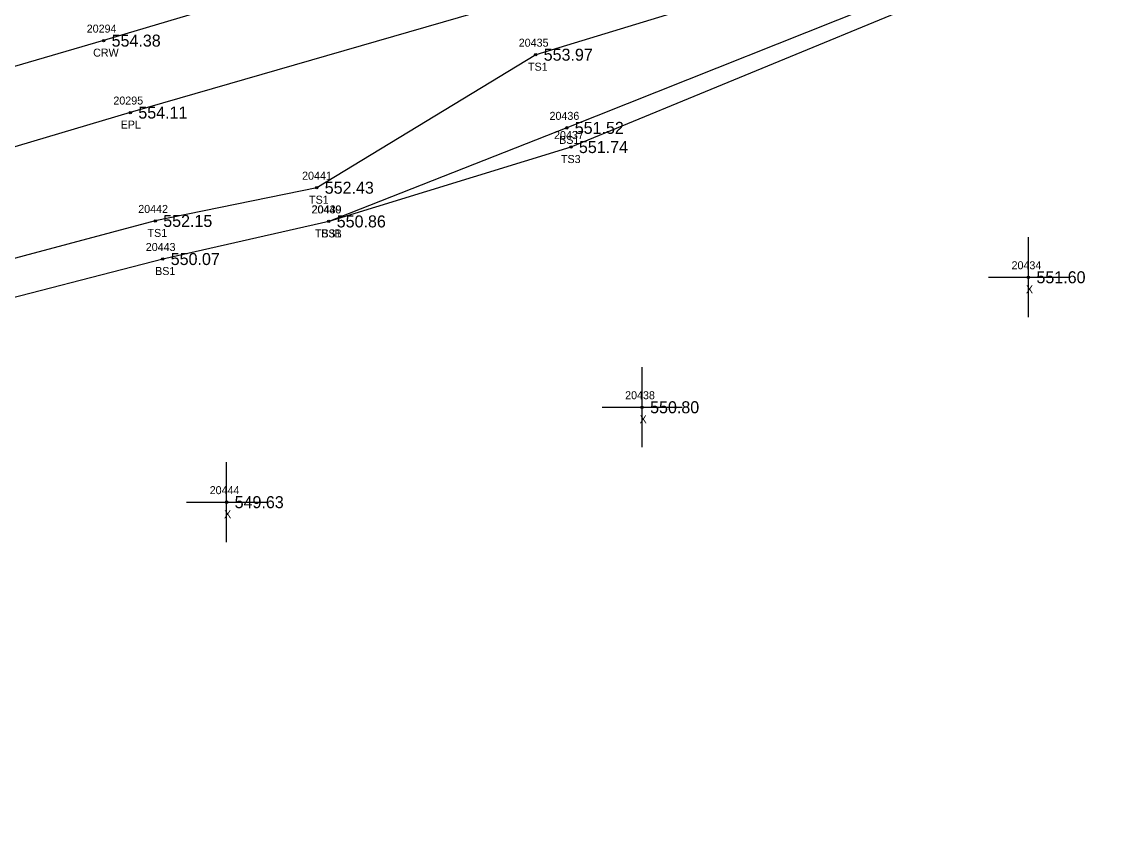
# Model space of a CAD drawing. Extents: x 1540443 to 1541844, y 887157 to 888162.
# Drawn here: x 1541377.9 to 1541515.8, y 887652.8 to 887753.4 of the extents above; entities that cross this region are included whole.
import ezdxf

# ---------------------------------------------------------------- set-up
doc = ezdxf.new("R2010")
doc.units = 0
for name, color, linetype in [('RD_DTM_BkLn1', 7, 'Continuous'), ('RD_DTM_BkLn2', 7, 'Continuous'), ('RD_DTM_BkLn_txCode', 7, 'Continuous'), ('RD_EX_Misc', 7, 'Continuous'), ('RD_EX_Misc_txCode', 7, 'Continuous'), ('RD_EX_Road', 7, 'Continuous'), ('RD_EX_Road_txCode', 7, 'Continuous'), ('RD_EX_TX_Misc_ELEV', 7, 'Continuous'), ('RD_EX_TX_Road_ELEV', 7, 'Continuous'), ('RD_HC_Survey_ELEV', 7, 'Continuous'), ('RD_HC_Survey_txCode', 7, 'Continuous'), ('RD_SMD_Locator', 7, 'Continuous')]:
    doc.layers.add(name, color=color, linetype=linetype)

msp = doc.modelspace()

# ---------------------------------------------------------------- linework, layer by layer
at = {"layer": 'RD_DTM_BkLn1'}
msp.add_lwpolyline([(1541819.64, 887879.04), (1541771.84, 887865.01), (1541723.55, 887850.95), (1541675.82, 887836.26), (1541627.89, 887822.08), (1541580.01, 887807.87), (1541531.93, 887793.38), (1541484.13, 887778.91), (1541435.66, 887765.21), (1541388.1, 887751.04), (1541339.55, 887736.89), (1541291.46, 887723.08), (1541243.5, 887708.82), (1541195.27, 887694.78), (1541169.43, 887686.85)], dxfattribs=at)
at = {"layer": 'RD_DTM_BkLn2'}
for points in [[(1541824.97, 887864.95), (1541773.24, 887848.9), (1541728.33, 887834.59), (1541680.22, 887820.65), (1541632.2, 887806.6), (1541586.15, 887794.2), (1541535.56, 887777.78), (1541490.03, 887763.87), (1541442.11, 887749.28), (1541414.74, 887732.66), (1541394.55, 887728.51), (1541346.01, 887715.56), (1541298.68, 887704.05), (1541256.52, 887687.99), (1541253.67, 887682.12), (1541204.18, 887671.81), (1541185.24, 887668.7), (1541173.43, 887674.53)], [(1541826.01, 887862.16), (1541773.99, 887846.34), (1541729.05, 887832.97), (1541681.03, 887818.46), (1541632.94, 887804.51), (1541587.44, 887789.41), (1541536.78, 887773.27), (1541491.06, 887758.08), (1541445.99, 887740.14), (1541416.24, 887728.45), (1541395.49, 887723.75), (1541347.04, 887711.22), (1541300.85, 887696.02), (1541261.64, 887680.26), (1541255.59, 887675.42), (1541206.42, 887663.07), (1541174, 887652.79)], [(1541826.81, 887859.86), (1541774.16, 887844.66), (1541729.81, 887830.83), (1541681.55, 887816.28), (1541633.12, 887801.68), (1541588.74, 887788.35), (1541537.56, 887771.08), (1541491.43, 887756.24), (1541446.51, 887737.74), (1541416.24, 887728.45)]]:
    msp.add_lwpolyline(points, dxfattribs=at)
at = {"layer": 'RD_EX_Misc'}
for p, q in [((1541503.7, 887716.47), (1541503.7, 887726.47)), ((1541498.7, 887721.47), (1541508.7, 887721.47)), ((1541455.41, 887700.23), (1541455.41, 887710.23)), ((1541450.41, 887705.23), (1541460.41, 887705.23)), ((1541403.48, 887688.37), (1541403.48, 887698.37)), ((1541398.48, 887693.37), (1541408.48, 887693.37))]:
    msp.add_line(p, q, dxfattribs=at)
at = {"layer": 'RD_EX_Road'}
msp.add_lwpolyline([(1541823.08, 887870.08), (1541774.23, 887855.6), (1541726.64, 887841.16), (1541678.89, 887827.09), (1541630.15, 887812.57), (1541582.93, 887798.43), (1541534.59, 887784.1), (1541487.04, 887769.99), (1541438.64, 887755.66), (1541391.44, 887742.05), (1541342.36, 887727.48), (1541295.07, 887713.91), (1541246.74, 887699.66), (1541197.81, 887684.79), (1541172.48, 887676.63)], dxfattribs=at)
at = {"layer": 'RD_SMD_Locator'}
for centre in [(1541388.1, 887751.04), (1541442.11, 887749.28), (1541391.44, 887742.05), (1541445.99, 887740.14), (1541446.51, 887737.74), (1541414.74, 887732.66), (1541394.55, 887728.51), (1541416.24, 887728.45), (1541416.24, 887728.45), (1541395.49, 887723.75), (1541503.7, 887721.47), (1541455.41, 887705.23), (1541403.48, 887693.37)]:
    msp.add_circle(centre, 0.15, dxfattribs=at)

# ---------------------------------------------------------------- texts
at = {"layer": 'RD_DTM_BkLn_txCode'}
for s, p in [('20435', (1541439.99, 887750.28)), ('TS1', (1541441.15, 887747.28)), ('20436', (1541443.84, 887741.14)), ('20437', (1541444.4, 887738.74)), ('BS1', (1541445.04, 887738.14)), ('TS3', (1541445.27, 887735.74)), ('20441', (1541412.91, 887733.66)), ('20442', (1541392.43, 887729.51)), ('TS1', (1541413.78, 887730.66)), ('20440', (1541414.08, 887729.45)), ('20439', (1541414.12, 887729.45)), ('TS1', (1541393.59, 887726.51)), ('TS3B', (1541414.52, 887726.45)), ('BS1', (1541415.3, 887726.45)), ('20443', (1541393.37, 887724.75)), ('BS1', (1541394.54, 887721.75))]:
    msp.add_text(s, height=1, dxfattribs=at).set_placement(p)
at = {"layer": 'RD_EX_Misc_txCode'}
for s, p in [('20434', (1541501.59, 887722.47)), ('X', (1541503.39, 887719.47)), ('20438', (1541453.29, 887706.23)), ('X', (1541455.1, 887703.23)), ('20444', (1541401.36, 887694.37)), ('X', (1541403.16, 887691.37))]:
    msp.add_text(s, height=1, dxfattribs=at).set_placement(p)
at = {"layer": 'RD_EX_Road_txCode'}
for s, p in [('20295', (1541389.32, 887743.05)), ('EPL', (1541390.23, 887740.05))]:
    msp.add_text(s, height=1, dxfattribs=at).set_placement(p)
at = {"layer": 'RD_EX_TX_Misc_ELEV'}
for s, p in [('553.97', (1541443.11, 887748.53)), ('551.52', (1541446.99, 887739.39)), ('551.74', (1541447.51, 887736.99)), ('552.43', (1541415.74, 887731.91)), ('552.15', (1541395.55, 887727.76)), ('550.86', (1541417.24, 887727.7)), ('550.86', (1541417.24, 887727.7)), ('550.07', (1541396.49, 887723)), ('551.60', (1541504.7, 887720.72)), ('550.80', (1541456.41, 887704.48)), ('549.63', (1541404.48, 887692.62))]:
    msp.add_text(s, height=1.5, dxfattribs=at).set_placement(p)
at = {"layer": 'RD_EX_TX_Road_ELEV'}
msp.add_text('554.11', height=1.5, dxfattribs=at).set_placement((1541392.44, 887741.3))
at = {"layer": 'RD_HC_Survey_ELEV'}
msp.add_text('554.38', height=1.5, dxfattribs=at).set_placement((1541389.1, 887750.29))
at = {"layer": 'RD_HC_Survey_txCode'}
for s, p in [('20294', (1541385.99, 887752.04)), ('CRW', (1541386.79, 887749.04))]:
    msp.add_text(s, height=1, dxfattribs=at).set_placement(p)

doc.saveas('drawing.dxf')
